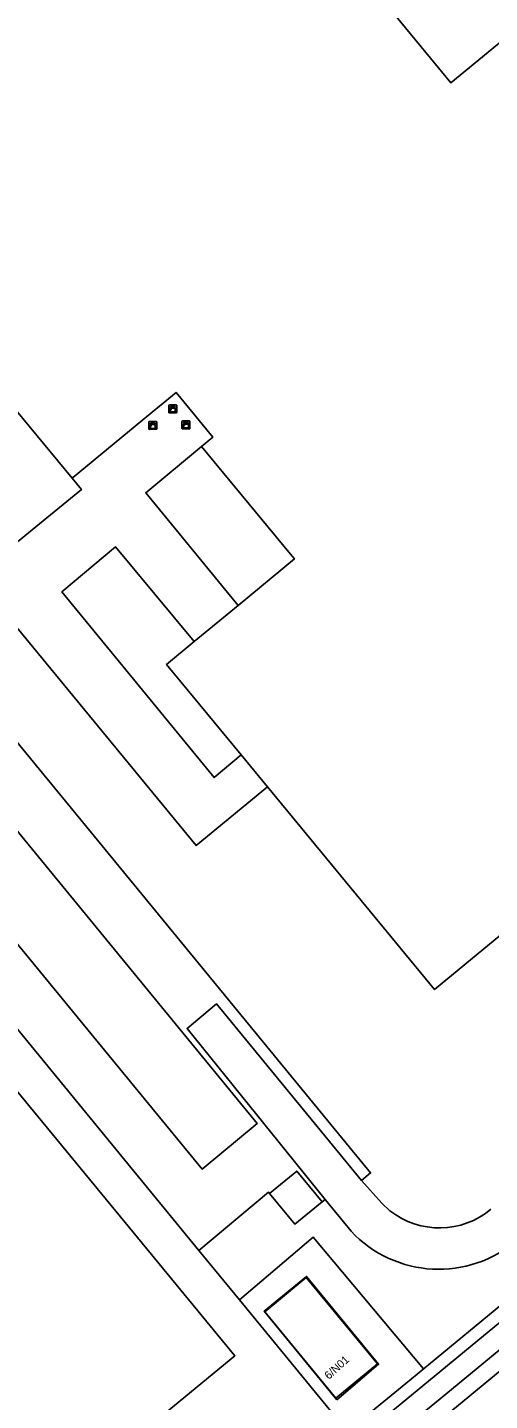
# Model space of a CAD drawing. Extents: x 156141 to 158132, y 385651 to 388399.
# Drawn here: x 157186.6 to 157244.4, y 386478.5 to 386650.1 of the extents above; entities that cross this region are included whole.
import ezdxf

# ---------------------------------------------------------------- set-up
doc = ezdxf.new("R2010")
doc.units = 0
for name, color, linetype in [('IMGEO_Erf', 7, 'Continuous'), ('IMGEO_Fietspad_gesloten', 7, 'Continuous'), ('IMGEO_Hek', 7, 'Continuous'), ('IMGEO_Kast', 7, 'Continuous'), ('IMGEO_Pand', 7, 'Continuous'), ('IMGEO_Pand_nummerreeks', 7, 'Continuous'), ('IMGEO_Pand_vergunning_verleend', 7, 'Continuous'), ('IMGEO_Parkeervlak_open', 7, 'Continuous'), ('IMGEO_Rijbaan_lokaal_gesloten', 7, 'Continuous'), ('IMGEO_Rijbaan_lokaal_open', 7, 'Continuous'), ('IMGEO_Voetpad_open', 7, 'Continuous')]:
    doc.layers.add(name, color=color, linetype=linetype)

msp = doc.modelspace()

# ---------------------------------------------------------------- linework, layer by layer
at = {"layer": 'IMGEO_Erf'}
msp.add_lwpolyline([(157226.61, 386474.61), (157213.1, 386491.07), (157208.03, 386497.24)], dxfattribs=at)
at = {"layer": 'IMGEO_Fietspad_gesloten'}
for points in [[(157225.9, 386471.96), (157236.74, 386480.89), (157259.95, 386500), (157294.79, 386528.69), (157379.64, 386598.54)], [(157296.44, 386526.68), (157264.04, 386500), (157238.17, 386478.7), (157234.6, 386475.76)]]:
    msp.add_lwpolyline(points, dxfattribs=at)
at = {"layer": 'IMGEO_Hek'}
msp.add_lwpolyline([(157213.1, 386491.07), (157222.33, 386498.88), (157236.11, 386482.43)], dxfattribs=at)
at = {"layer": 'IMGEO_Kast'}
for p, q in [((157204.26, 386601.98), (157204.26, 386602.82)), ((157204.26, 386602.82), (157204.26, 386601.98)), ((157204.34, 386602.91), (157205.18, 386602.91)), ((157205.18, 386602.91), (157204.34, 386602.91)), ((157205.19, 386601.91), (157204.35, 386601.91)), ((157204.35, 386601.91), (157205.19, 386601.91)), ((157205.26, 386602.83), (157205.26, 386601.99)), ((157205.26, 386601.99), (157205.26, 386602.83)), ((157201.76, 386599.93), (157201.76, 386600.77)), ((157201.76, 386600.77), (157201.76, 386599.93)), ((157201.84, 386600.85), (157202.68, 386600.85)), ((157202.68, 386600.85), (157201.84, 386600.85)), ((157202.69, 386599.86), (157201.85, 386599.86)), ((157201.85, 386599.86), (157202.69, 386599.86)), ((157202.76, 386600.78), (157202.76, 386599.94)), ((157202.76, 386599.94), (157202.76, 386600.78)), ((157205.91, 386599.98), (157205.91, 386600.82)), ((157205.91, 386600.82), (157205.91, 386599.98)), ((157205.99, 386600.91), (157206.83, 386600.91)), ((157206.83, 386600.91), (157205.99, 386600.91)), ((157206.84, 386599.91), (157206, 386599.91)), ((157206, 386599.91), (157206.84, 386599.91)), ((157206.91, 386600.83), (157206.91, 386599.99)), ((157206.91, 386599.99), (157206.91, 386600.83))]:
    msp.add_line(p, q, dxfattribs=at)
for points in [[(157204.46, 386602.7), (157205.06, 386602.7), (157205.06, 386602.61), (157204.46, 386602.61), (157204.46, 386602.7)], [(157204.46, 386602.52), (157205.06, 386602.52), (157205.06, 386602.03), (157204.46, 386602.03), (157204.46, 386602.52)], [(157201.96, 386600.65), (157202.56, 386600.65), (157202.56, 386600.56), (157201.96, 386600.56), (157201.96, 386600.65)], [(157201.96, 386600.47), (157202.56, 386600.47), (157202.56, 386599.98), (157201.96, 386599.98), (157201.96, 386600.47)], [(157206.11, 386600.7), (157206.71, 386600.7), (157206.71, 386600.61), (157206.11, 386600.61), (157206.11, 386600.7)], [(157206.11, 386600.52), (157206.71, 386600.52), (157206.71, 386600.03), (157206.11, 386600.03), (157206.11, 386600.52)]]:
    msp.add_lwpolyline(points, dxfattribs=at)
for centre in [(157204.54, 386602.37), (157202.04, 386600.32), (157206.19, 386600.37)]:
    msp.add_circle(centre, 0.0377, dxfattribs=at)
for centre, start, end in [((157204.34, 386602.83), 92.4484, 184.2845), ((157204.34, 386602.83), 92.4484, 184.2845), ((157204.34, 386601.98), 182.4484, 274.2845), ((157204.34, 386601.98), 182.4484, 274.2845), ((157205.18, 386602.83), 2.4484, 94.2845), ((157205.18, 386602.83), 2.4484, 94.2845), ((157205.18, 386601.98), 272.4484, 4.2845), ((157205.18, 386601.98), 272.4484, 4.2845), ((157201.84, 386600.78), 92.4484, 184.2845), ((157201.84, 386600.78), 92.4484, 184.2845), ((157201.84, 386599.93), 182.4484, 274.2845), ((157201.84, 386599.93), 182.4484, 274.2845), ((157202.69, 386600.78), 2.4484, 94.2845), ((157202.69, 386600.78), 2.4484, 94.2845), ((157202.69, 386599.93), 272.4484, 4.2845), ((157202.69, 386599.93), 272.4484, 4.2845), ((157205.99, 386600.83), 92.4484, 184.2845), ((157205.99, 386600.83), 92.4484, 184.2845), ((157205.99, 386599.99), 182.4484, 274.2845), ((157205.99, 386599.99), 182.4484, 274.2845), ((157206.83, 386600.83), 2.4484, 94.2845), ((157206.83, 386600.83), 2.4484, 94.2845), ((157206.83, 386599.99), 272.4484, 4.2845), ((157206.83, 386599.99), 272.4484, 4.2845)]:
    msp.add_arc(centre, 0.0779, start, end, dxfattribs=at)
at = {"layer": 'IMGEO_Pand'}
for points in [[(157186.93, 386707.01), (157239.52, 386643.16), (157264.92, 386664.1)], [(157305.19, 386652.34), (157328.57, 386623.96), (157330.05, 386625.19), (157333.04, 386621.57), (157326.95, 386616.54), (157327.99, 386615.32), (157327.85, 386615.21), (157325.92, 386617.51), (157324.72, 386616.53), (157326.63, 386614.2), (157339.73, 386598.21), (157295.95, 386562.12), (157267.48, 386596.65), (157267.16, 386597.04), (157261.75, 386592.58), (157272.2, 386579.91), (157282.73, 386567.14), (157237.49, 386529.84), (157216.6, 386555.17)], [(157167.99, 386623.07), (157168.08, 386622.96), (157185.02, 386602.41), (157192.17, 386593.74)], [(157192.17, 386593.74), (157201.01, 386601.04), (157205.18, 386604.48), (157207.7, 386601.41), (157209.77, 386598.89), (157208.36, 386597.72)], [(157208.36, 386597.72), (157219.27, 386584.49), (157219.96, 386583.66), (157212.92, 386577.85)], [(157212.92, 386577.85), (157207.45, 386573.33)], [(157207.45, 386573.33), (157203.98, 386570.47), (157213.3, 386559.18)], [(157213.3, 386559.18), (157216.6, 386555.17)], [(157116.21, 386500), (157127.1, 386508.96), (157133.36, 386514.12), (157165.78, 386540.8), (157199.38, 386500), (157212.51, 386484.05), (157183.01, 386459.8), (157181.86, 386461.2), (157166.86, 386448.84), (157138.86, 386425.77), (157126.75, 386415.79), (157110.04, 386436.12), (157108.67, 386434.94), (157079.79, 386470.01), (157116.21, 386500)], [(157230.33, 386483.05), (157225.14, 386478.78), (157216.28, 386489.57), (157221.44, 386493.87), (157230.33, 386483.05)]]:
    msp.add_lwpolyline(points, dxfattribs=at)
at = {"layer": 'IMGEO_Pand_vergunning_verleend'}
msp.add_lwpolyline([(157225.26, 386478.56), (157216.19, 386489.64), (157221.49, 386493.98), (157230.48, 386483.01), (157225.26, 386478.56)], dxfattribs=at)
at = {"layer": 'IMGEO_Parkeervlak_open'}
msp.add_lwpolyline([(157216.85, 386504.35), (157220.03, 386500.5), (157223.42, 386503.29)], dxfattribs=at)
at = {"layer": 'IMGEO_Rijbaan_lokaal_gesloten'}
for points in [[(157223.8, 386503.61), (157206.54, 386524.99), (157210.23, 386528.05), (157228.35, 386505.99)], [(157297.77, 386525.08), (157267.32, 386500), (157239.52, 386477.11), (157235.94, 386474.16)], [(157228.35, 386505.99), (157230.88, 386503.14), (157231.91, 386502.18)], [(157227.04, 386499.66), (157223.8, 386503.61)]]:
    msp.add_lwpolyline(points, dxfattribs=at)
for centre, radius, start, end in [((157238.09, 386510.07), 10.02, 231.9386, 310.0045), ((157238.01, 386509.86), 14.98, 222.9286, 311.103)]:
    msp.add_arc(centre, radius, start, end, dxfattribs=at)
at = {"layer": 'IMGEO_Rijbaan_lokaal_open'}
for points in [[(157208.36, 386597.72), (157201.38, 386591.93), (157212.92, 386577.85)], [(157192.17, 386593.74), (157193.35, 386592.32), (157176.19, 386578.33), (157176.51, 386577.93), (157174.65, 386576.4)], [(157154.75, 386586.93), (157215.33, 386513.1), (157208.43, 386507.39), (157147.76, 386581.25), (157154.75, 386586.93)], [(157207.45, 386573.33), (157197.59, 386585.18), (157190.91, 386579.53), (157209.92, 386556.34), (157213.3, 386559.18)], [(157208.03, 386497.24), (157151.72, 386565.87), (157139.12, 386581.23)], [(157216.6, 386555.17), (157207.68, 386547.85), (157185.27, 386575.09), (157178.36, 386569.18), (157229.49, 386506.92), (157228.35, 386505.99)], [(157216.85, 386504.35), (157220.26, 386507.15), (157223.42, 386503.29)], [(157208.03, 386497.24), (157216.73, 386504.5), (157216.85, 386504.35)], [(157223.42, 386503.29), (157223.8, 386503.61)]]:
    msp.add_lwpolyline(points, dxfattribs=at)
at = {"layer": 'IMGEO_Voetpad_open'}
msp.add_lwpolyline([(157226.61, 386474.61), (157226.82, 386474.79), (157233.89, 386480.6), (157236.03, 386482.36), (157257.45, 386500), (157293.78, 386529.91), (157370.16, 386592.8)], dxfattribs=at)

# ---------------------------------------------------------------- texts
at = {"layer": 'IMGEO_Pand_nummerreeks'}
msp.add_text('6/N01', height=1, rotation=42.337, dxfattribs=at).set_placement((157224.27, 386481.04))

doc.saveas('drawing.dxf')
